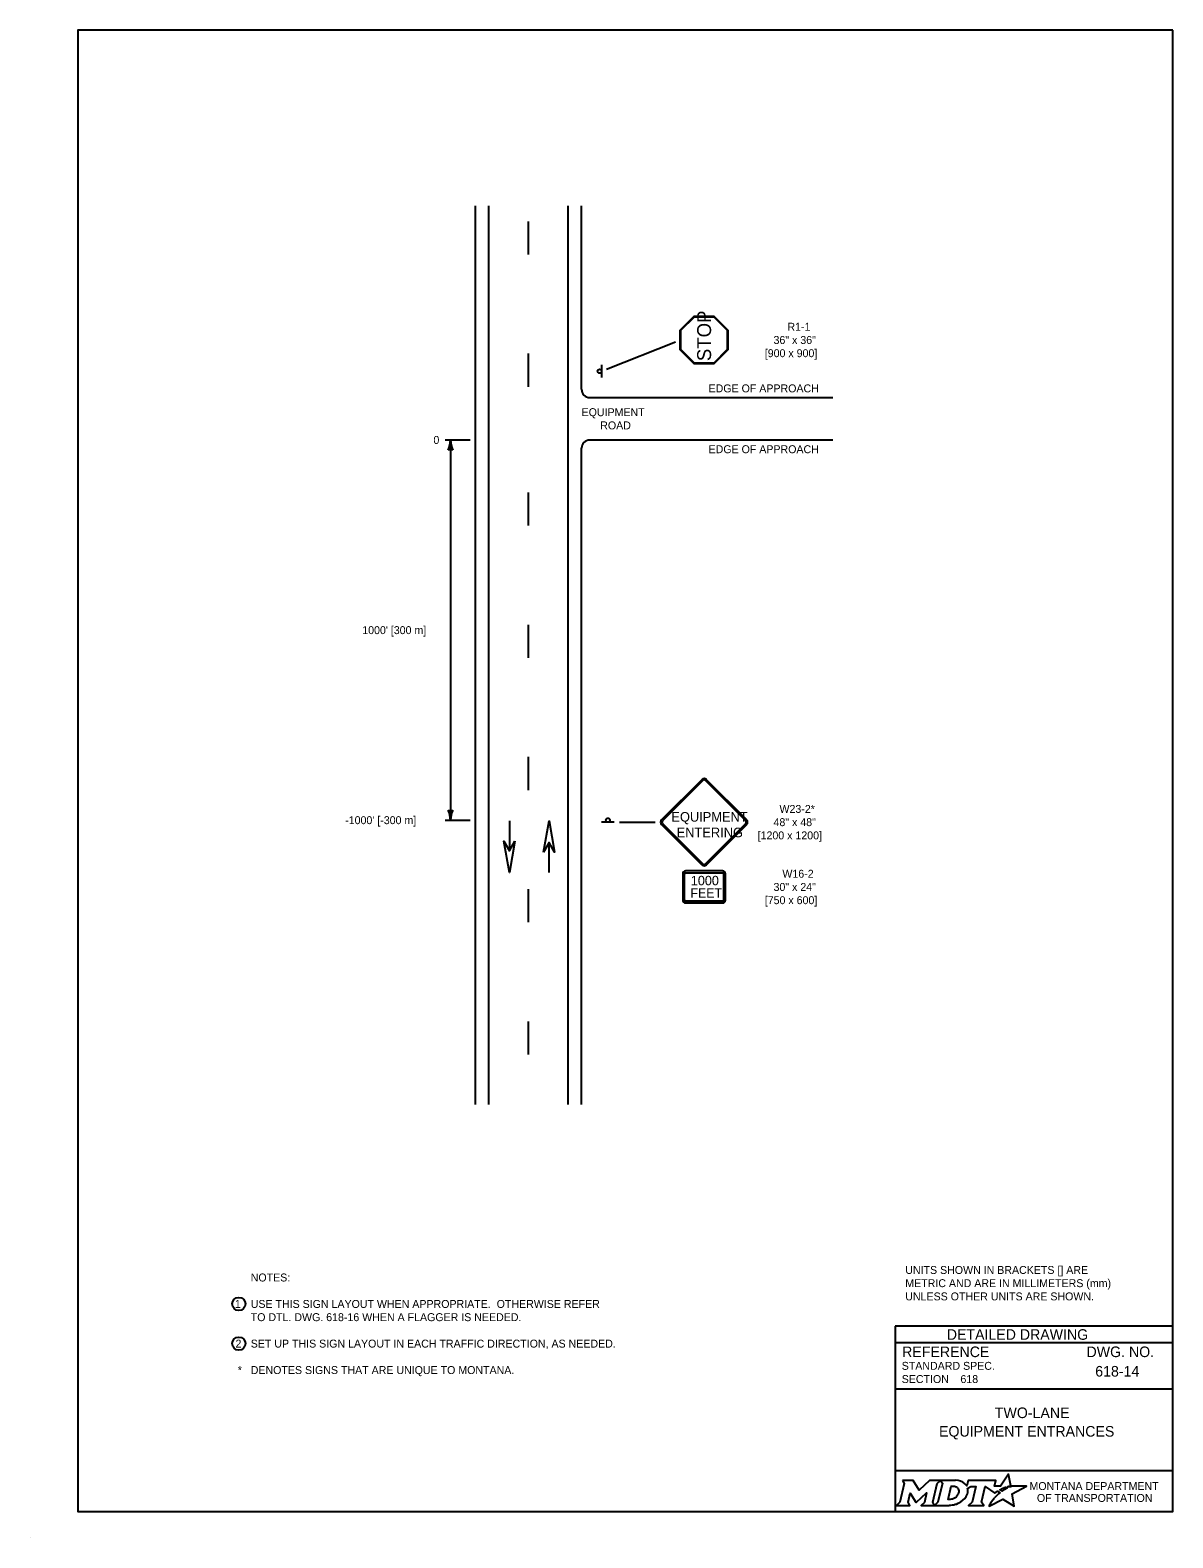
# Model space of a CAD drawing. Extents: x 49991.4 to 50021, y 49987.6 to 50011.4.
# Drawn here: x 49999.98 to 50008.61, y 49999.86 to 50011.26 of the extents above; entities that cross this region are included whole.
import ezdxf

# ---------------------------------------------------------------- set-up
doc = ezdxf.new("R2010")
doc.units = 0
for name, color, linetype in [('Level 1', 7, 'Continuous'), ('Level 2', 7, 'Continuous'), ('Level 25', 7, 'Continuous'), ('Level 3', 7, 'Continuous'), ('Level 7', 7, 'Continuous')]:
    doc.layers.add(name, color=color, linetype=linetype)

msp = doc.modelspace()

# ---------------------------------------------------------------- linework, layer by layer
at = {"layer": 'Level 1'}
for p, q in [((50003.344, 50003.138), (50003.344, 50009.934)), ((50003.444, 50003.138), (50003.444, 50009.934)), ((50004.044, 50003.138), (50004.044, 50009.934)), ((50004.144, 50008.547), (50004.144, 50009.934)), ((50003.744, 50009.567), (50003.744, 50009.817)), ((50003.744, 50008.567), (50003.744, 50008.817)), ((50004.296, 50008.732), (50004.296, 50008.636)), ((50004.207, 50008.484), (50006.044, 50008.484)), ((50004.144, 50003.138), (50004.144, 50008.101)), ((50004.207, 50008.164), (50006.044, 50008.164)), ((50003.744, 50007.517), (50003.744, 50007.767)), ((50003.744, 50006.517), (50003.744, 50006.767)), ((50003.744, 50005.517), (50003.744, 50005.767)), ((50005.054, 50005.595), (50004.75, 50005.291)), ((50005.061, 50005.588), (50004.757, 50005.284)), ((50005.386, 50005.284), (50005.082, 50005.588)), ((50005.393, 50005.291), (50005.089, 50005.595)), ((50004.392, 50005.274), (50004.296, 50005.274)), ((50004.75, 50005.256), (50005.054, 50004.952)), ((50004.757, 50005.263), (50005.061, 50004.959)), ((50005.082, 50004.959), (50005.386, 50005.263)), ((50005.089, 50004.952), (50005.393, 50005.256)), ((50003.744, 50004.517), (50003.744, 50004.767)), ((50003.744, 50003.517), (50003.744, 50003.767)), ((49999.977, 49999.862), (49999.977, 49999.862))]:
    msp.add_line(p, q, dxfattribs=at)
for points in [[(50008.615, 50011.263), (50000.336, 50011.263), (50000.336, 50000.062), (50008.615, 50000.062)], [(50004.891, 50008.846), (50004.891, 50008.995), (50004.997, 50009.1), (50005.146, 50009.1), (50005.251, 50008.995), (50005.251, 50008.846), (50005.146, 50008.74), (50004.997, 50008.74)], [(50004.896, 50008.848), (50004.896, 50008.993), (50004.999, 50009.095), (50005.144, 50009.095), (50005.246, 50008.993), (50005.246, 50008.848), (50005.144, 50008.745), (50004.999, 50008.745)]]:
    msp.add_lwpolyline(points, close=True, dxfattribs=at)
for centre in [(50004.281, 50008.684), (50004.344, 50005.289)]:
    msp.add_circle(centre, 0.0152, dxfattribs=at)
for centre, radius, start, end in [((50004.207, 50008.547), 0.0625, 180, 270), ((50004.207, 50008.101), 0.0625, 90, 180), ((50005.071, 50005.578), 0.025, 45, 135), ((50005.071, 50005.578), 0.015, 45, 135), ((50004.767, 50005.274), 0.025, 135, 225), ((50004.767, 50005.274), 0.015, 135, 225), ((50005.375, 50005.274), 0.015, 315, 45.0002), ((50005.375, 50005.274), 0.025, 315, 45.0002), ((50005.071, 50004.97), 0.025, 225, 314.9996), ((50005.071, 50004.97), 0.015, 225, 314.9996)]:
    msp.add_arc(centre, radius, start, end, dxfattribs=at)
at = {"layer": 'Level 2'}
for p, q in [((50008.615, 50001.462), (50006.515, 50001.462)), ((50006.515, 50001.462), (50006.515, 50000.062)), ((50008.615, 50001.337), (50006.515, 50001.337)), ((50007.009, 50001.063), (50007.009, 50001.063)), ((50008.251, 50001.122), (50008.251, 50001.122)), ((50008.615, 50000.987), (50006.515, 50000.987)), ((50007.565, 50000.738), (50007.565, 50000.738)), ((50008.615, 50000.369), (50006.515, 50000.369))]:
    msp.add_line(p, q, dxfattribs=at)
for points in [[(50007.377, 50000.245), (50007.367, 50000.25), (50007.378, 50000.253), (50007.39, 50000.255), (50007.373, 50000.345), (50007.313, 50000.254), (50007.266, 50000.253), (50007.276, 50000.297), (50007.067, 50000.297), (50007.057, 50000.255), (50007.051, 50000.263)], [(50006.57, 50000.297), (50006.584, 50000.274), (50006.551, 50000.131), (50006.525, 50000.108), (50006.627, 50000.108), (50006.613, 50000.131), (50006.629, 50000.201), (50006.673, 50000.132), (50006.678, 50000.132), (50006.753, 50000.202), (50006.737, 50000.13), (50006.712, 50000.108), (50006.814, 50000.108), (50006.8, 50000.132), (50006.833, 50000.274)], [(50006.833, 50000.274), (50006.859, 50000.297), (50006.776, 50000.297), (50006.697, 50000.224), (50006.652, 50000.297), (50006.57, 50000.297)], [(50006.972, 50000.297), (50006.859, 50000.297), (50006.873, 50000.275), (50006.839, 50000.131), (50006.814, 50000.108), (50006.925, 50000.108)], [(50006.996, 50000.211), (50006.995, 50000.203), (50006.992, 50000.193), (50006.988, 50000.185), (50006.982, 50000.178), (50006.976, 50000.171), (50006.968, 50000.164), (50006.959, 50000.16), (50006.95, 50000.156), (50006.941, 50000.154), (50006.932, 50000.153), (50006.916, 50000.153), (50006.94, 50000.253), (50006.956, 50000.253), (50006.963, 50000.252), (50006.971, 50000.25), (50006.977, 50000.247), (50006.983, 50000.243), (50006.988, 50000.238), (50006.992, 50000.232), (50006.995, 50000.226), (50006.996, 50000.218), (50006.996, 50000.215), (50006.996, 50000.211)], [(50007.064, 50000.238), (50007.088, 50000.251), (50007.125, 50000.251), (50007.097, 50000.131), (50007.069, 50000.108), (50007.185, 50000.108), (50007.168, 50000.131), (50007.196, 50000.251), (50007.268, 50000.2), (50007.289, 50000.215), (50007.309, 50000.204)], [(50007.253, 50000.148), (50007.237, 50000.124), (50007.233, 50000.116), (50007.227, 50000.107), (50007.225, 50000.103), (50007.33, 50000.156), (50007.414, 50000.101), (50007.401, 50000.194), (50007.508, 50000.252), (50007.458, 50000.253), (50007.428, 50000.253), (50007.407, 50000.254), (50007.401, 50000.252), (50007.396, 50000.251), (50007.387, 50000.249), (50007.377, 50000.245)], [(50007.327, 50000.217), (50007.324, 50000.215), (50007.306, 50000.225), (50007.316, 50000.231), (50007.32, 50000.233), (50007.329, 50000.237), (50007.335, 50000.239), (50007.343, 50000.243), (50007.35, 50000.245), (50007.362, 50000.238), (50007.358, 50000.236), (50007.353, 50000.233), (50007.349, 50000.231), (50007.344, 50000.228), (50007.342, 50000.227), (50007.339, 50000.225), (50007.337, 50000.224), (50007.334, 50000.222), (50007.332, 50000.221), (50007.329, 50000.219), (50007.327, 50000.217)], [(50006.97, 50000.116), (50006.979, 50000.118), (50006.992, 50000.124), (50007.012, 50000.135)], [(50007.267, 50000.164), (50007.267, 50000.164)]]:
    msp.add_lwpolyline(points, dxfattribs=at)
for centre in [(50001.554, 50001.631), (50001.554, 50001.331)]:
    msp.add_circle(centre, 0.05, dxfattribs=at)
for centre, radius, start, end in [((50006.995, 50000.219), 0.0709, 339.5329, 15.8582), ((50006.951, 50000.236), 0.118, 300.9103, 339.1383)]:
    msp.add_arc(centre, radius, start, end, dxfattribs=at)
for centre, major_axis, ratio, start_param, end_param in [((50006.97, 50000.25), (0.0834, -0.0037), 0.568097, 0.61298, 1.570796), ((50007.026, 50000.257), (0.0361, -0.0295), 0.469099, 1.225588, 1.570796), ((50006.925, 50000.257), (0, 0.148), 0.987302, 3.139398, 3.456847), ((50007.26, 50000.156), (-0.00694, -0.00806), 0.008222, 0, 3.137361), ((50007.276, 50000.174), (-0.0098, -0.0102), 0.016458, 3.141593, 6.279097), ((50007.297, 50000.194), (-0.0112, -0.0097), 0.021651, 3.157348, 6.283185)]:
    msp.add_ellipse(centre, major_axis=major_axis, ratio=ratio, start_param=start_param, end_param=end_param, dxfattribs=at)
at = {"layer": 'Level 25'}
for p, q in [((50005.212, 50004.905), (50004.93, 50004.905)), ((50004.93, 50004.891), (50005.212, 50004.891)), ((50004.91, 50004.884), (50004.91, 50004.683)), ((50004.923, 50004.683), (50004.923, 50004.884)), ((50005.219, 50004.884), (50005.219, 50004.683)), ((50005.233, 50004.683), (50005.233, 50004.884)), ((50005.212, 50004.676), (50004.93, 50004.676)), ((50004.93, 50004.663), (50005.212, 50004.663))]:
    msp.add_line(p, q, dxfattribs=at)
for centre, radius, start, end in [((50004.93, 50004.884), 0.0202, 90, 180), ((50004.93, 50004.884), 0.00672, 90, 180), ((50005.212, 50004.884), 0.0202, 0, 90), ((50005.212, 50004.884), 0.00672, 0, 90), ((50004.93, 50004.683), 0.0202, 180, 270), ((50004.93, 50004.683), 0.00672, 180, 270), ((50005.212, 50004.683), 0.00672, 270, 360), ((50005.212, 50004.683), 0.0202, 270, 360)]:
    msp.add_arc(centre, radius, start, end, dxfattribs=at)
at = {"layer": 'Level 3'}
for p, q in [((50004.333, 50008.699), (50004.854, 50008.906)), ((50003.114, 50008.164), (50003.304, 50008.164)), ((50003.154, 50008.164), (50003.154, 50005.289)), ((50003.114, 50005.289), (50003.304, 50005.289)), ((50004.432, 50005.274), (50004.702, 50005.274))]:
    msp.add_line(p, q, dxfattribs=at)
for centre, radius, start, end in [((50002.932, 50008.173), 0.222, 337.456, 357.6395), ((50003.154, 50008.036), 0.0548, 72.1388, 107.8612), ((50003.387, 50008.175), 0.233, 182.8273, 202.0772), ((50003.154, 50005.417), 0.0548, 252.1388, 287.8612), ((50002.921, 50005.277), 0.233, 2.8273, 22.0772), ((50003.376, 50005.28), 0.222, 157.456, 177.6395)]:
    msp.add_arc(centre, radius, start, end, dxfattribs=at)
at = {"layer": 'Level 7'}
for p, q in [((50003.599, 50005.283), (50003.599, 50005.057)), ((50003.6, 50005.283), (50003.6, 50005.057)), ((50003.899, 50004.893), (50003.899, 50005.119)), ((50003.899, 50004.893), (50003.899, 50005.119))]:
    msp.add_line(p, q, dxfattribs=at)
for points in [[(50003.857, 50005.047), (50003.899, 50005.283), (50003.941, 50005.047), (50003.899, 50005.119)], [(50003.641, 50005.13), (50003.6, 50004.893), (50003.558, 50005.13), (50003.6, 50005.057)]]:
    msp.add_lwpolyline(points, close=True, dxfattribs=at)

# ---------------------------------------------------------------- texts
at = {"layer": 'Level 1'}
msp.add_text('STOP', height=0.1051, rotation=90, dxfattribs=at).set_placement((50005.124, 50008.76))
for s, p in [('EQUIPMENT', (50004.824, 50005.278)), ('ENTERING', (50004.864, 50005.16))]:
    msp.add_text(s, height=0.0725, dxfattribs=at).set_placement(p)
at = {"layer": 'Level 2'}
for s, height, p in [('R1-1', 0.06, (50005.701, 50008.99)), ('36" x 36"', 0.06, (50005.596, 50008.89)), ('[900 x 900]', 0.06, (50005.53, 50008.79)), ('EDGE OF APPROACH', 0.06, (50005.105, 50008.524)), ('EQUIPMENT', 0.06, (50004.145, 50008.344)), ('ROAD', 0.06, (50004.286, 50008.244)), ('0', 0.06, (50003.025, 50008.134)), ('EDGE OF APPROACH', 0.06, (50005.105, 50008.064)), ("1000' [300 m]", 0.06, (50002.487, 50006.696)), ('W23-2*', 0.06, (50005.641, 50005.344)), ("-1000' [-300 m]", 0.06, (50002.358, 50005.259)), ('48" x 48"', 0.06, (50005.596, 50005.244)), ('[1200 x 1200]', 0.06, (50005.476, 50005.144)), ('W16-2', 0.06, (50005.663, 50004.854)), ('30" x 24"', 0.06, (50005.596, 50004.754)), ('[750 x 600]', 0.06, (50005.53, 50004.654)), ('NOTES:', 0.06, (50001.644, 50001.801)), ('UNITS SHOWN IN BRACKETS [] ARE ', 0.06, (50006.592, 50001.858)), ('METRIC AND ARE IN MILLIMETERS (mm) ', 0.06, (50006.592, 50001.758)), ('UNLESS OTHER UNITS ARE SHOWN.', 0.06, (50006.592, 50001.658)), ('1', 0.06, (50001.524, 50001.601)), ('USE THIS SIGN LAYOUT WHEN APPROPRIATE.  OTHERWISE REFER ', 0.06, (50001.644, 50001.601)), ('TO DTL. DWG. 618-16 WHEN A FLAGGER IS NEEDED.', 0.06, (50001.644, 50001.501)), ('2', 0.06, (50001.529, 50001.301)), ('SET UP THIS SIGN LAYOUT IN EACH TRAFFIC DIRECTION, AS NEEDED.', 0.06, (50001.644, 50001.301)), ('DETAILED DRAWING', 0.0799, (50006.906, 50001.36)), ('REFERENCE', 0.08, (50006.568, 50001.229)), ('DWG. NO.', 0.08, (50007.962, 50001.229)), ('*', 0.06, (50001.546, 50001.101)), ('DENOTES SIGNS THAT ARE UNIQUE TO MONTANA.', 0.06, (50001.644, 50001.101)), ('STANDARD SPEC.', 0.06, (50006.565, 50001.133)), ('618-14', 0.08, (50008.028, 50001.082)), ('SECTION', 0.06, (50006.565, 50001.033)), ('618', 0.06, (50007.009, 50001.033)), ('TWO-LANE', 0.08, (50007.269, 50000.768)), ('EQUIPMENT ENTRANCES', 0.08, (50006.847, 50000.628)), ('MONTANA DEPARTMENT', 0.06, (50007.531, 50000.224)), ('OF TRANSPORTATION', 0.06, (50007.587, 50000.134))]:
    msp.add_text(s, height=height, dxfattribs=at).set_placement(p)
at = {"layer": 'Level 25'}
for s, height, p in [('1000', 0.0712, (50004.971, 50004.797)), ('FEET', 0.0699, (50004.968, 50004.703))]:
    msp.add_text(s, height=height, dxfattribs=at).set_placement(p)

doc.saveas('drawing.dxf')
